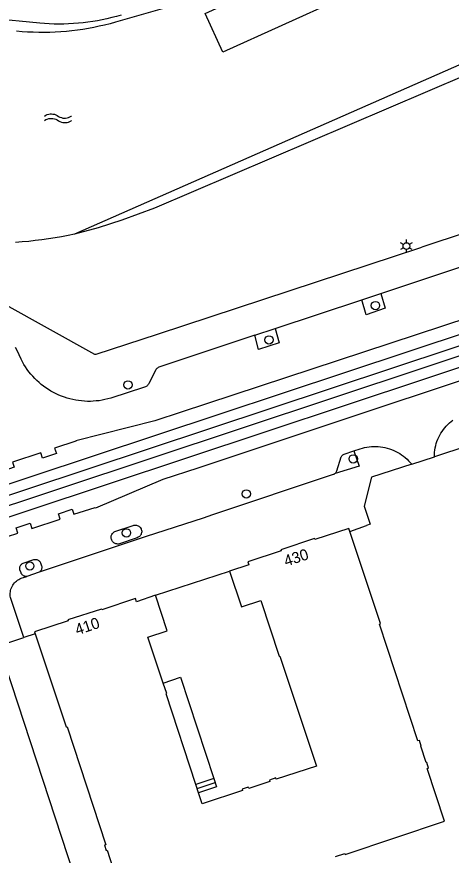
# Model space of a CAD drawing. Extents: x 122462 to 123306, y 485548 to 486417.
# Drawn here: x 122924.9 to 122983.5, y 486167.9 to 486281.1 of the extents above; entities that cross this region are included whole.
import ezdxf

# ---------------------------------------------------------------- set-up
doc = ezdxf.new("R2010")
doc.units = 0
for name, color, linetype in [('Level 1', 7, 'Continuous'), ('Level 12', 7, 'Continuous'), ('Level 16', 7, 'Continuous'), ('Level 17', 7, 'Continuous'), ('Level 19', 7, 'Continuous'), ('Level 23', 7, 'Continuous'), ('Level 30', 7, 'Continuous'), ('Level 31', 7, 'Continuous'), ('Level 33', 7, 'Continuous'), ('Level 37', 7, 'Continuous'), ('Level 50', 7, 'Continuous'), ('Level 53', 7, 'Continuous'), ('Level 55', 7, 'Continuous'), ('Level 58', 7, 'Continuous')]:
    doc.layers.add(name, color=color, linetype=linetype)

msp = doc.modelspace()

# ---------------------------------------------------------------- linework, layer by layer
at = {"layer": 'Level 1'}
msp.add_line((122949.42, 486176.31), (122949.06, 486177.43), dxfattribs=at)
for points in [[(122969.84, 486211.57), (122969.7, 486211.99), (122965.13, 486210.49), (122965.09, 486210.62), (122960.52, 486209.12), (122960.56, 486208.99), (122956.08, 486207.51), (122956.22, 486207.1), (122953.62, 486206.25)], [(122967.91, 486167.68), (122969.17, 486168.1), (122969.22, 486167.99), (122982.62, 486172.46), (122980.28, 486179.59), (122980.48, 486179.65), (122980.23, 486180.41), (122980.14, 486180.38), (122979.42, 486182.59), (122979.5, 486182.61), (122979.25, 486183.37), (122979.05, 486183.31), (122973.86, 486199.08), (122973.98, 486199.14), (122969.84, 486211.57)], [(122953.62, 486206.25), (122955.22, 486201.43), (122957.82, 486202.28), (122960.31, 486194.73), (122960.39, 486194.75), (122965.34, 486179.91), (122959.9, 486178.12), (122959.84, 486178.3), (122958.99, 486178.02), (122959.05, 486177.84), (122956.2, 486176.9), (122956.14, 486177.08), (122955.3, 486176.8), (122955.36, 486176.62), (122949.91, 486174.83), (122949.42, 486176.31)], [(122943.62, 486202.97), (122941.05, 486202.11), (122940.91, 486202.53), (122936.36, 486201.03), (122936.33, 486201.12), (122931.8, 486199.64), (122931.83, 486199.54), (122927.29, 486198.04), (122927.38, 486197.77)], [(122944.67, 486191.12), (122942.6, 486197.31), (122945.17, 486198.18), (122943.62, 486202.97)], [(122927.38, 486197.77), (122931.54, 486185.2), (122931.67, 486185.2), (122936.9, 486169.29), (122936.71, 486169.23), (122936.95, 486168.5), (122937.09, 486168.55), (122937.83, 486166.29), (122937.69, 486166.24), (122937.92, 486165.55), (122938.11, 486165.61), (122940.47, 486158.43), (122957.01, 486163.96)], [(122949.06, 486177.43), (122945.05, 486189.65), (122945.15, 486189.69), (122944.67, 486191.12)]]:
    msp.add_lwpolyline(points, dxfattribs=at)
at = {"layer": 'Level 12'}
msp.add_lwpolyline([(122952.71, 486276.29), (122950.32, 486281.52), (122966.24, 486288.81), (122968.63, 486283.58), (122952.71, 486276.29)], dxfattribs=at)
at = {"layer": 'Level 16'}
for points in [[(123077.51, 486315.81), (123061.12, 486307.75), (123059.81, 486307.11), (123041.02, 486298.31), (123000.65, 486281.69), (122991.32, 486277.54), (122932.68, 486251.75)], [(122950.18, 486283.84), (122938.2, 486280.35), (122937.48, 486280.15), (122936.75, 486279.97), (122936.02, 486279.8), (122935.29, 486279.65), (122934.55, 486279.51), (122933.81, 486279.39), (122933.07, 486279.28), (122932.33, 486279.19), (122931.59, 486279.12), (122930.84, 486279.06), (122930.09, 486279.01), (122929.34, 486278.98), (122928.59, 486278.97), (122927.85, 486278.97), (122927.1, 486278.99), (122926.35, 486279.02), (122925.6, 486279.07), (122924.86, 486279.14)], [(122932.68, 486251.75), (122931.81, 486251.57), (122930.93, 486251.39), (122930.05, 486251.24), (122929.17, 486251.1), (122928.28, 486250.97), (122927.39, 486250.86), (122926.51, 486250.76), (122925.61, 486250.68), (122924.72, 486250.61)]]:
    msp.add_lwpolyline(points, dxfattribs=at)
at = {"layer": 'Level 17'}
for p, q in [((122971.48, 486242.88), (122974.04, 486243.73)), ((122959.79, 486239), (122971.48, 486242.88)), ((122957.03, 486238.09), (122959.79, 486239)), ((122927.9, 486206.09), (122926.23, 486205.52)), ((122922.4, 486196.15), (122925.85, 486197.27)), ((122927.38, 486197.77), (122925.85, 486197.27))]:
    msp.add_line(p, q, dxfattribs=at)
for points in [[(123076.09, 486310.66), (123083.14, 486293.07), (123083.2, 486292.91), (123083.23, 486292.75), (123083.25, 486292.59), (123083.26, 486292.42), (123083.26, 486292.25), (123083.23, 486292.09), (123083.2, 486291.93), (123083.15, 486291.77), (123083.08, 486291.62), (123083.01, 486291.47), (123082.91, 486291.33), (123082.81, 486291.2), (123082.7, 486291.08), (123082.58, 486290.97), (123066.19, 486278.64), (123065.49, 486278.37), (123044.45, 486271.17), (123000.15, 486256.61), (122998.02, 486255.79), (122997.93, 486256.04), (122979.58, 486250)], [(123014.47, 486250), (123003.57, 486246.31), (122947.09, 486227.72), (122943.53, 486226.54), (122932.85, 486223.85), (122932.86, 486223.79), (122930, 486222.82), (122930.23, 486222.12), (122928.35, 486221.49), (122928.12, 486222.2), (122924.29, 486220.94), (122924.52, 486220.25), (122922.66, 486219.6), (122922.4, 486220.31), (122919.56, 486219.39), (122919.51, 486219.46), (122909.36, 486215.2), (122892.23, 486209.6)], [(122910.46, 486250), (122910.56, 486249.62), (122910.6, 486249.51), (122910.66, 486249.41), (122910.74, 486249.31), (122910.82, 486249.23), (122910.91, 486249.15), (122911.01, 486249.09), (122935.36, 486235.53), (122935.61, 486235.52), (122943.89, 486238.25), (122979.58, 486250)], [(122974.04, 486243.73), (122987, 486248.03), (122986.95, 486248.11), (122986.92, 486248.19), (122986.9, 486248.28), (122986.89, 486248.37), (122986.9, 486248.47), (122986.92, 486248.56), (122986.96, 486248.64), (122987, 486248.72), (122987.06, 486248.79), (122987.13, 486248.85), (122987.21, 486248.9), (122987.3, 486248.94), (122990.51, 486250)], [(122894.79, 486202.01), (122911.48, 486207.66), (122922.2, 486210.37), (122922.19, 486210.44), (122925.05, 486211.37), (122924.8, 486212.09), (122926.68, 486212.73), (122926.9, 486212.01), (122930.74, 486213.27), (122930.5, 486213.98), (122932.38, 486214.62), (122932.61, 486213.93), (122935.49, 486214.83), (122935.54, 486214.76), (122944.66, 486218.64), (122949.38, 486220.2), (123005.98, 486239.05), (123026.44, 486245.79)], [(122974.04, 486243.73), (122974.63, 486241.74), (122972.07, 486240.82), (122971.48, 486242.88)], [(122957.03, 486238.09), (122945.14, 486234.14), (122944.18, 486233.82), (122944.08, 486233.78), (122943.98, 486233.72), (122943.88, 486233.65), (122943.8, 486233.58), (122943.72, 486233.49), (122943.65, 486233.4), (122942.73, 486231.56), (122942.67, 486231.47), (122942.6, 486231.37), (122942.53, 486231.29), (122942.44, 486231.22), (122942.35, 486231.15), (122942.25, 486231.1), (122942.14, 486231.06), (122937.57, 486229.58), (122937.18, 486229.48), (122936.79, 486229.39), (122936.4, 486229.31), (122936.01, 486229.25), (122935.62, 486229.21), (122935.22, 486229.18), (122934.82, 486229.16), (122934.42, 486229.16), (122934.03, 486229.18), (122933.63, 486229.21), (122933.24, 486229.26), (122932.84, 486229.32), (122932.45, 486229.4), (122932.07, 486229.49), (122931.68, 486229.6), (122931.31, 486229.72), (122930.93, 486229.86), (122930.56, 486230.01), (122930.2, 486230.17), (122929.85, 486230.35), (122929.5, 486230.55), (122929.16, 486230.75), (122928.83, 486230.97), (122928.51, 486231.21), (122928.19, 486231.45), (122927.89, 486231.71), (122927.59, 486231.97), (122927.31, 486232.25), (122927.04, 486232.54), (122926.78, 486232.84), (122926.53, 486233.15), (122926.29, 486233.47), (122926.07, 486233.8), (122925.86, 486234.14), (122925.66, 486234.49), (122925.48, 486234.84), (122924.94, 486236.01), (122924.71, 486236.45)], [(122959.79, 486239), (122960.31, 486237.07), (122957.54, 486236.16), (122957.03, 486238.09)], [(123018.17, 486233.86), (123008.74, 486230.74), (122999.54, 486227.68), (122981.26, 486221.69)], [(122981.26, 486221.69), (122981.26, 486221.99), (122981.28, 486222.29), (122981.32, 486222.59), (122981.37, 486222.89), (122981.44, 486223.18), (122981.52, 486223.48), (122981.61, 486223.76), (122981.72, 486224.05), (122981.85, 486224.32), (122981.98, 486224.59), (122982.13, 486224.86), (122982.29, 486225.11), (122982.47, 486225.36), (122982.65, 486225.6), (122982.85, 486225.83), (122983.06, 486226.05), (122983.28, 486226.26), (122983.51, 486226.46), (122983.75, 486226.64)], [(122970.39, 486222.47), (122971.1, 486220.4), (122967.89, 486219.43)], [(122967.89, 486219.43), (122967.96, 486219.5), (122968.02, 486219.59), (122968.07, 486219.68), (122968.11, 486219.78), (122968.69, 486221.65), (122968.73, 486221.73), (122968.78, 486221.82), (122968.84, 486221.89), (122968.91, 486221.95), (122968.99, 486222), (122969.08, 486222.04), (122970.39, 486222.47)], [(122970.39, 486222.47), (122971.25, 486222.75), (122971.54, 486222.84), (122971.84, 486222.92), (122972.14, 486222.97), (122972.45, 486223.02), (122972.76, 486223.05), (122973.06, 486223.06), (122973.37, 486223.06), (122973.68, 486223.05), (122973.99, 486223.02), (122974.29, 486222.97), (122974.59, 486222.91), (122974.89, 486222.84), (122975.19, 486222.75), (122975.48, 486222.65), (122975.77, 486222.53), (122976.05, 486222.4), (122976.32, 486222.26), (122976.59, 486222.11), (122976.84, 486221.94), (122977.09, 486221.76), (122977.33, 486221.56), (122977.57, 486221.36), (122977.79, 486221.14), (122978, 486220.92), (122978.2, 486220.68)], [(122978.2, 486220.68), (122972.77, 486218.91), (122971.77, 486214.99), (122972.58, 486212.59), (122972.12, 486212.41)], [(122967.89, 486219.43), (122967.8, 486219.36), (122967.7, 486219.3), (122967.6, 486219.26), (122951.31, 486213.83), (122950.03, 486213.4), (122942.35, 486210.93), (122927.9, 486206.09)], [(122938.51, 486209.89), (122938.39, 486209.9), (122938.28, 486209.92), (122938.17, 486209.96), (122938.07, 486210.01), (122937.98, 486210.07), (122937.89, 486210.14), (122937.81, 486210.23), (122937.75, 486210.32), (122937.7, 486210.43), (122937.66, 486210.53), (122937.63, 486210.64), (122937.62, 486210.76), (122937.63, 486210.87), (122937.65, 486210.99), (122937.68, 486211.09), (122937.73, 486211.2), (122937.79, 486211.3), (122937.86, 486211.38), (122937.94, 486211.46), (122938.04, 486211.53), (122938.14, 486211.59), (122940.6, 486212.4), (122940.71, 486212.43), (122940.82, 486212.44), (122940.94, 486212.44), (122941.05, 486212.43), (122941.16, 486212.4), (122941.26, 486212.36), (122941.36, 486212.3), (122941.45, 486212.23), (122941.53, 486212.15), (122941.6, 486212.06), (122941.66, 486211.96), (122941.7, 486211.86), (122941.73, 486211.75), (122941.75, 486211.63), (122941.75, 486211.52), (122941.73, 486211.41), (122941.7, 486211.3), (122941.66, 486211.19), (122941.6, 486211.09), (122941.53, 486211), (122941.45, 486210.92), (122941.36, 486210.85), (122941.26, 486210.8), (122941.16, 486210.75), (122938.62, 486209.89), (122938.51, 486209.89)], [(122926.23, 486205.52), (122926.08, 486205.53), (122925.98, 486205.54), (122925.88, 486205.57), (122925.79, 486205.62), (122925.7, 486205.67), (122925.62, 486205.74), (122925.56, 486205.82), (122925.5, 486205.91), (122925.46, 486206), (122925.32, 486206.42), (122925.3, 486206.52), (122925.29, 486206.62), (122925.29, 486206.72), (122925.31, 486206.81), (122925.34, 486206.91), (122925.39, 486207), (122925.44, 486207.08), (122925.51, 486207.15), (122925.59, 486207.22), (122925.67, 486207.27), (122925.76, 486207.31), (122927.2, 486207.79), (122927.3, 486207.81), (122927.4, 486207.82), (122927.5, 486207.82), (122927.59, 486207.8), (122927.69, 486207.77), (122927.78, 486207.73), (122927.86, 486207.67), (122927.93, 486207.6), (122928, 486207.53), (122928.05, 486207.44), (122928.09, 486207.35), (122928.23, 486206.93), (122928.25, 486206.84), (122928.26, 486206.74), (122928.26, 486206.64), (122928.24, 486206.54), (122928.21, 486206.45), (122928.17, 486206.36), (122928.12, 486206.28), (122928.06, 486206.21), (122927.98, 486206.14), (122927.9, 486206.09)], [(122925.85, 486197.27), (122924.05, 486202.68), (122924.01, 486202.87), (122924, 486203.06), (122924, 486203.25), (122924.02, 486203.44), (122924.05, 486203.62), (122924.1, 486203.81), (122924.17, 486203.99), (122924.25, 486204.16), (122924.34, 486204.33), (122924.45, 486204.49), (122924.56, 486204.64), (122924.7, 486204.78), (122924.84, 486204.9), (122924.99, 486205.02), (122925.15, 486205.12), (122925.32, 486205.21), (122925.5, 486205.28), (122926.23, 486205.52)]]:
    msp.add_lwpolyline(points, dxfattribs=at)
at = {"layer": 'Level 19'}
for points in [[(123075.83, 486311.01), (123063.29, 486306.13), (123062.23, 486305.59), (123060.88, 486304.91), (123052.94, 486301.86), (123043.53, 486298.03), (122943.5, 486255.26), (122939.06, 486253.61), (122935.89, 486252.58), (122932.68, 486251.75)], [(122938.96, 486281.32), (122938.33, 486281.14), (122937.7, 486280.97), (122937.06, 486280.82), (122936.43, 486280.68), (122935.79, 486280.56), (122935.14, 486280.45), (122934.49, 486280.35), (122933.85, 486280.27), (122933.2, 486280.21), (122932.55, 486280.16), (122931.89, 486280.12), (122931.24, 486280.11), (122930.59, 486280.1), (122929.93, 486280.11), (122929.28, 486280.14), (122928.63, 486280.18), (122927.98, 486280.24), (122921.41, 486280.87), (122912.91, 486282.25)]]:
    msp.add_lwpolyline(points, dxfattribs=at)
at = {"layer": 'Level 23'}
for p, q in [((122978.2, 486220.68), (122981.26, 486221.69)), ((122969.84, 486211.57), (122972.12, 486212.41)), ((122943.62, 486202.97), (122953.62, 486206.25)), ((122922.4, 486196.15), (122939.61, 486144.05))]:
    msp.add_line(p, q, dxfattribs=at)
at = {"layer": 'Level 30'}
msp.add_line((122951.49, 486178.23), (122949.06, 486177.43), dxfattribs=at)
msp.add_lwpolyline([(122944.67, 486191.12), (122947.01, 486191.9), (122951.49, 486178.23)], dxfattribs=at)
at = {"layer": 'Level 31'}
msp.add_lwpolyline([(122951.49, 486178.23), (122951.86, 486177.11), (122949.42, 486176.31)], dxfattribs=at)
at = {"layer": 'Level 33'}
msp.add_line((122949.24, 486176.87), (122951.67, 486177.67), dxfattribs=at)
at = {"layer": 'Level 37'}
for points in [[(122892.85, 486207.77), (123020.2, 486250)], [(123024.9, 486250), (122893.32, 486206.37)], [(123028.9, 486250), (122893.74, 486205.11)], [(123033.6, 486250), (122894.22, 486203.71)]]:
    msp.add_lwpolyline(points, dxfattribs=at)
at = {"layer": 'Level 50'}
for p, q in [((122977.09, 486250.36), (122976.7, 486250.58)), ((122977.48, 486250.58), (122977.48, 486251.03)), ((122978.26, 486250.58), (122977.87, 486250.36)), ((122977.09, 486249.91), (122976.7, 486249.68)), ((122977.48, 486249.23), (122977.48, 486249.68)), ((122978.26, 486249.68), (122977.87, 486249.91))]:
    msp.add_line(p, q, dxfattribs=at)
msp.add_circle((122977.48, 486250.13), 0.45, dxfattribs=at)
at = {"layer": 'Level 53'}
for centre in [(122973.31, 486242.09), (122958.93, 486237.46), (122939.9, 486231.38), (122970.31, 486221.39), (122955.88, 486216.66), (122939.69, 486211.4), (122926.65, 486206.93)]:
    msp.add_circle(centre, 0.56, dxfattribs=at)
at = {"layer": 'Level 55'}
for points in [[(122928.63, 486267.69), (122928.82, 486267.8), (122929.01, 486267.88), (122929.2, 486267.94), (122929.39, 486267.97), (122929.58, 486267.97), (122929.77, 486267.96), (122929.96, 486267.92), (122930.15, 486267.85), (122930.34, 486267.76), (122930.53, 486267.63), (122930.72, 486267.54), (122930.91, 486267.47), (122931.1, 486267.42), (122931.29, 486267.4), (122931.48, 486267.4), (122931.67, 486267.43), (122931.86, 486267.48), (122932.05, 486267.56), (122932.24, 486267.66), (122932.27, 486267.68)], [(122928.63, 486267.09), (122928.82, 486267.2), (122929.01, 486267.28), (122929.2, 486267.34), (122929.39, 486267.37), (122929.58, 486267.37), (122929.77, 486267.36), (122929.96, 486267.32), (122930.15, 486267.25), (122930.34, 486267.16), (122930.53, 486267.03), (122930.72, 486266.93), (122930.91, 486266.87), (122931.1, 486266.82), (122931.29, 486266.8), (122931.48, 486266.8), (122931.67, 486266.83), (122931.86, 486266.88), (122932.05, 486266.96), (122932.24, 486267.06), (122932.27, 486267.09)]]:
    msp.add_lwpolyline(points, dxfattribs=at)

# ---------------------------------------------------------------- texts
at = {"layer": 'Level 58'}
for s, rotation, p in [('430', 18.2157, (122961.24, 486206.84)), ('410', 18.2731, (122933.04, 486197.57))]:
    msp.add_text(s, height=1.5, rotation=rotation, dxfattribs=at).set_placement(p)

doc.saveas('drawing.dxf')
